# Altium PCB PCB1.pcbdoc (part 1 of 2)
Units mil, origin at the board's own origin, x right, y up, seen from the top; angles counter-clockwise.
Board outline 1855 x 1070 mil, 2 copper layers (Top Layer, Bottom Layer), stack 62.206 mil thick; 23 components, 23 nets, 105 pads, 33 vias.
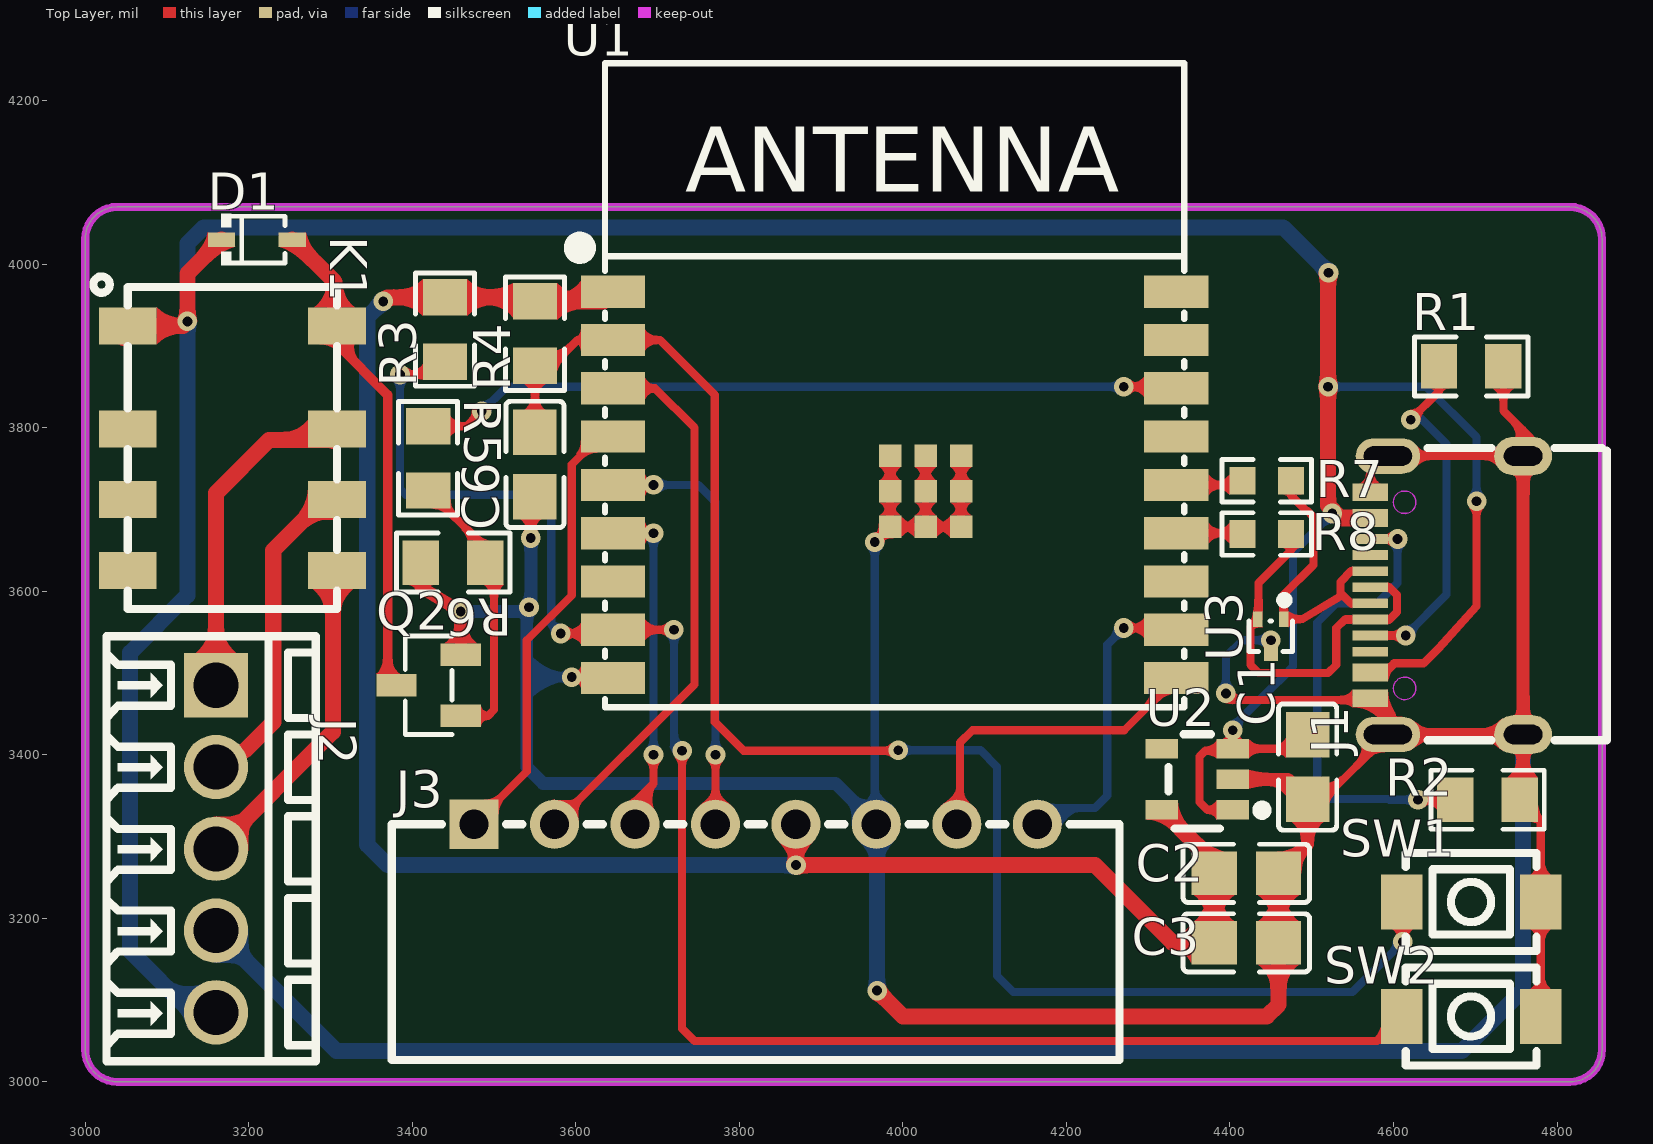
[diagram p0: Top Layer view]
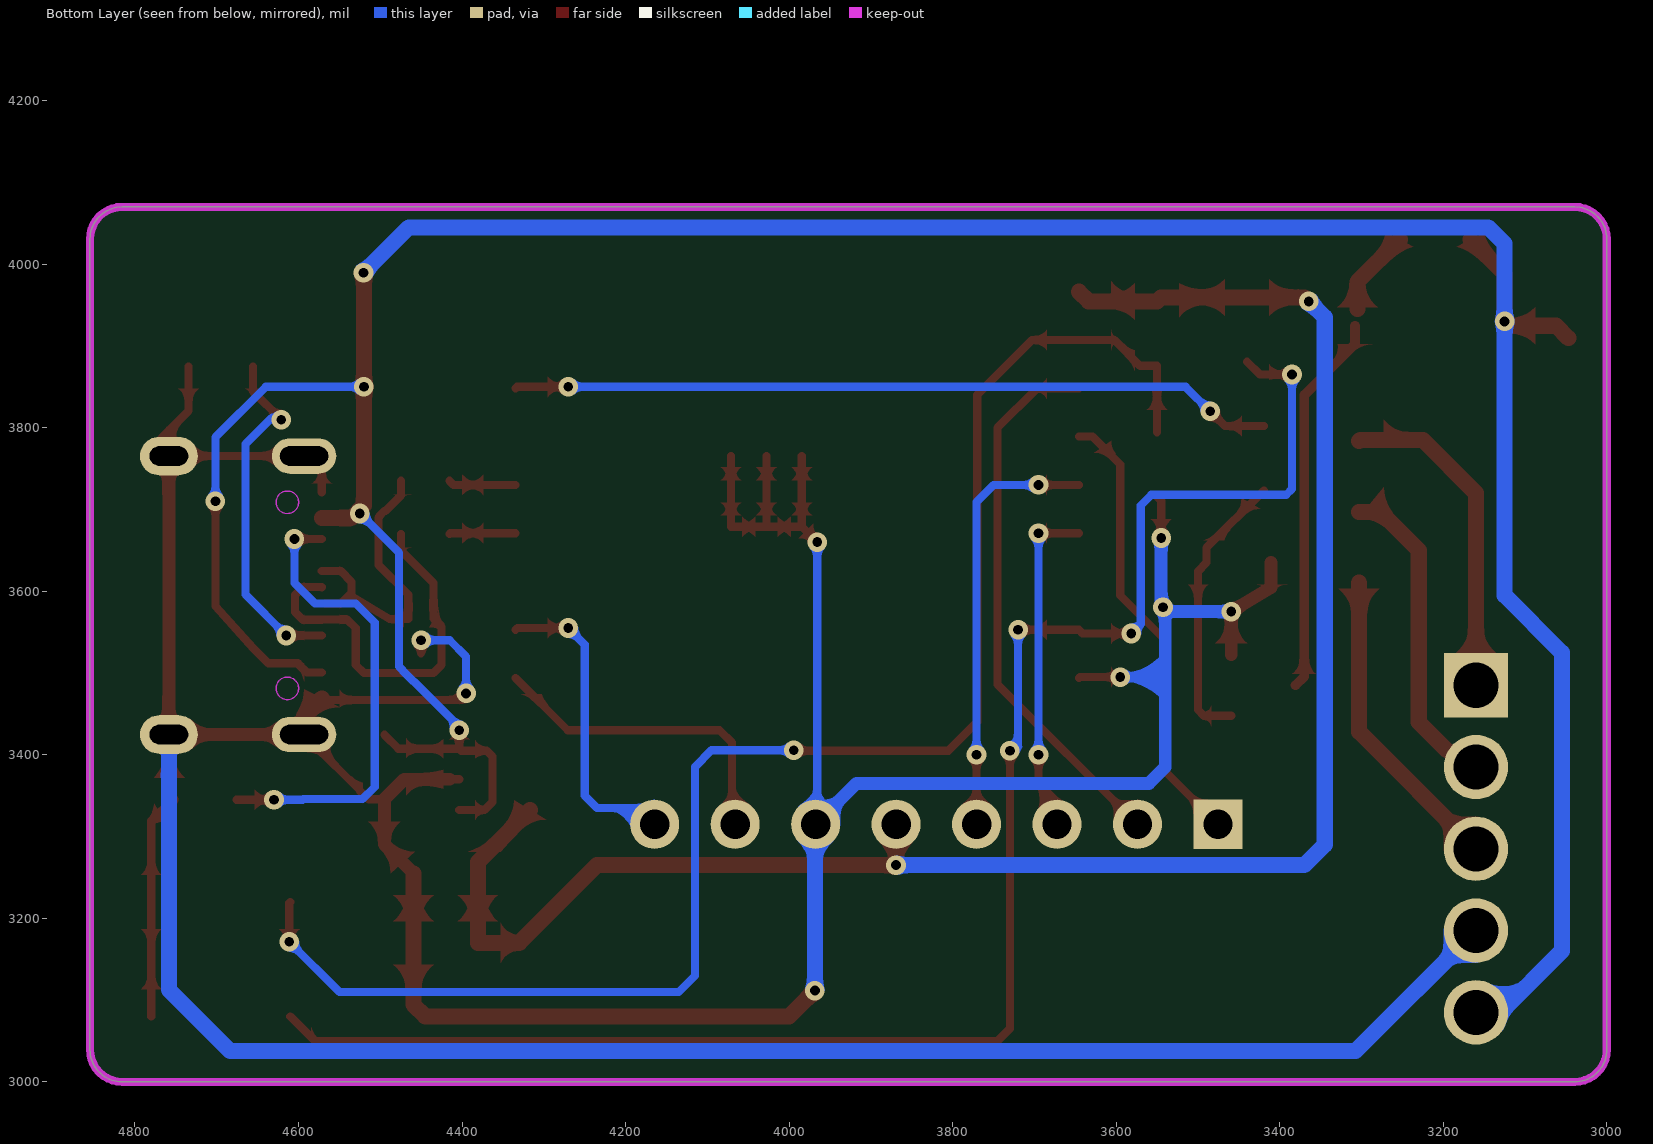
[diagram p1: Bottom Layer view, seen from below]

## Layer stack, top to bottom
Top Solder Mask Layer: solder mask 0.394, Dk 3.3
Top Layer: signal copper 1.379
Dielectric1: surface 59.449, FR4, Dk 4.5
Bottom Layer: signal copper 1.378
Bottom Solder Mask Layer: solder mask 0.394, Dk 3.3

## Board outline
3039.37,4070 4815.63,4070 cw(c4815.63,4030.63) 4855,4030.63 4855,3039.37 cw(c4815.63,3039.37) 4815.63,3000 3039.37,3000 cw(c3039.37,3039.37) 3000,3039.37 3000,4030.63 cw(c3039.37,4030.63)

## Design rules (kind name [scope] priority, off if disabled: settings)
BoardOutlineClearance copperThickness1oz [All] p0: genericclearance=10 ignorepadtopadclearanceinfootprint=FALSE except(0: Arc-SplitContinuation Track-SplitContinuation SMDPad-SplitContinuation THPad-SplitContinuation Via-SplitContinuation Fill-SplitContinuation Poly-SplitContinuation Region-SplitContinuation Text-SplitContinuation)
BoardOutlineClearance copperThickness2oz [All] p0: genericclearance=10 ignorepadtopadclearanceinfootprint=FALSE except(0: Arc-SplitContinuation Track-SplitContinuation SMDPad-SplitContinuation THPad-SplitContinuation Via-SplitContinuation Fill-SplitContinuation Poly-SplitContinuation Region-SplitContinuation Text-SplitContinuation)
BoardOutlineClearance otherClearance [All] p0: genericclearance=10 ignorepadtopadclearanceinfootprint=FALSE except(0: Arc-SplitContinuation Track-SplitContinuation SMDPad-SplitContinuation THPad-SplitContinuation Via-SplitContinuation Fill-SplitContinuation Poly-SplitContinuation Region-SplitContinuation Text-SplitContinuation)
Clearance copperThickness1oz [All] p1: gap=7 ignorepadtopadclearanceinfootprint=FALSE
Clearance copperThickness2oz [All] p1: gap=7 ignorepadtopadclearanceinfootprint=FALSE
Clearance otherClearance [All] p1: gap=7 ignorepadtopadclearanceinfootprint=FALSE
DiffPairsRouting differentialPair [All] p1: maxuncoupledlength=10 minlimit=6 maxlimit=Infinity mostfreqgap=6 toplayer_minwidth=5 toplayer_prefwidth=10 toplayer_maxwidth=100 bottomlayer_minwidth=5 bottomlayer_prefwidth=10 bottomlayer_maxwidth=100
PasteMaskExpansion pasteMaskExpansion [All] p1: expansion=0
PlaneConnect innerPlane [All] p1: planeconnectstyle=Relief reliefexpansion=20 reliefentries=4 reliefconductorwidth=10 reliefairgap=10
PolygonConnect copperRegion [All] p1: connectstyle=Relief reliefentries=4 reliefconductorwidth=10 polygonreliefangle="90 Angle" airgapwidth=10
RoutingVias viaSize [All] p1: viastyle="Through Hole" holewidth=12.0078 minholewidth=11.811 maxholewidth=248.0314 width=12.0078 minwidth=11.811 maxwidth=248.0314
SolderMaskExpansion solderMaskExpansion [All] p1: useseparateexpansions=TRUE expansion=2 expansionbottom=2
Width copperThickness1oz [All] p1: maxlimit=100 minlimit=5 preferedwidth=10
Width copperThickness2oz [All] p1: maxlimit=100 minlimit=8 preferedwidth=10

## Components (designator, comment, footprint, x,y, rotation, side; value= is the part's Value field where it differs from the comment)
C1 "" C0805 4495,3385 r90 top
C2 "" C0805 4420,3255 r0 top
C3 "" C0805 4420,3170 r180 top
C6 "" C0805 3550,3755 r90 top
D1 "" SOD-323_L1.7-W1.3-LS2.7-RD 3210,4030 r0 top
J1 "" USB-C-SMD_TYPE-C-6PIN-2MD-073 4665,3595 r90 top
J2 "" CONN-TH_XY308-2.54-5P 3160,3285 r270 top
J3 "" CONN-TH_8P-P2.50_ZX-XH2.54-8PWZ 3820,3315 r0 top
K1 "" RELAY-SMD_HFD4-5-S 3180,3775 r270 top
Q2 "" SOT-23-3_L2.9-W1.3-P1.90-LS2.4-BR 3420,3485 r0 top
R1 "" R0805 4695,3875 r0 top
R2 "" R0805 4715,3345 r0 top
R3 "" R0805 3440,3920 r90 top
R4 "" R0805 3550,3915 r90 top
R5 "" R0805 3419.42,3762.53 r270 top
R6 "" R0805 3450,3635 r180 top
R7 "" R0603 4445,3735 r0 top
R8 "" R0603 4445,3670 r0 top
SW1 "" KEY-SMD_L4.0-W3.0-LS4.9-1 4695,3220 r0 top
SW2 "" KEY-SMD_L4.0-W3.0-LS4.9-1 4695,3080 r0 top
U1 "" BULETM-SMD_ESPRESSIF_ESP32-C3-WROOM-02-N4-4MB 3990,3730 r0 top
U2 "" SOT-23-5_L2.9-W1.6-P0.95-LS2.8-BR 4360,3370 r0 top
U3 "" SOT-723_L1.2-W0.8-P0.80-LS1.2-BR 4450,3545 r90 top

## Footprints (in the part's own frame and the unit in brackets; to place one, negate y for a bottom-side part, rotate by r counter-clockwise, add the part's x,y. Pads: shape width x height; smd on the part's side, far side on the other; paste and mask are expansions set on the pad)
BULETM-SMD_ESPRESSIF_ESP32-C3-WROOM-02-N4-4MB [mm]
  rect 2x1 smd: 1(-8.75,6) 2(-8.75,4.5) 3(-8.75,3) 4(-8.75,1.5) 5(-8.75,0) 6(-8.75,-1.5) 7(-8.75,-3) 8(-8.75,-4.5) 9(-8.75,-6) 10(8.75,-6) 11(8.75,-4.5) 12(8.75,-3) 13(8.75,-1.5) 14(8.75,0) 15(8.75,1.5) 16(8.75,3) 17(8.75,4.5) 18(8.75,6)
  rect 0.7x0.7 smd: 19(-0.14,-1.3) 19(-0.14,-0.2) 19(-0.14,0.9) 19(0.96,-1.3) 19(0.96,-0.2) 19(0.96,0.9) 19(2.06,-1.3) 19(2.06,-0.2) 19(2.06,0.9)
  silkscreen extent -10.03,-6.9 9,13.1
C0805 [mm]
  rect 1.41x1.35 smd: 1(-1,0) 2(1,0)
  silkscreen extent -1.96,-0.9 1.96,0.9
CONN-TH_8P-P2.50_ZX-XH2.54-8PWZ [mil]
  rect 60x60 hole 36: 1(-344.49,0)
  round 60 hole 36: 2(-246.07,0) 3(-147.64,0) 4(-49.22,0) 5(49.21,0) 6(147.64,0) 7(246.06,0) 8(344.48,0)
  silkscreen extent -445,-288 445,0
CONN-TH_XY308-2.54-5P [mm]
  rect 2x2 hole 1.4: 1(-5.08,0)
  round 2 hole 1.4: 2(-2.54,0) 3(0,0) 4(2.54,0) 5(5.08,0)
  silkscreen extent -6.6,-3.4 6.6,3.1
KEY-SMD_L4.0-W3.0-LS4.9-1 [mm]
  rect 1.3x1.7 smd: 1(-2.159,0) 2(2.159,0)
  silkscreen extent -2.03,-1.52 2.03,1.52
R0603 [mil]
  rect 31.75x34.02 smd: 1(-29.66,0) 2(29.66,0)
  silkscreen extent -55,-26 55,26
R0805 [mm]
  rect 1.133x1.377 smd: 1(-1,0) 2(1,0)
  silkscreen extent -1.76,-0.92 1.76,0.92
RELAY-SMD_HFD4-5-S [mm]
  rect 1.15x1.8 smd: 1(-3.8,-3.25) 2(-0.6,-3.25) 3(1.6,-3.25) 4(3.8,-3.25) 5(3.8,3.25) 6(1.6,3.25) 7(-0.6,3.25) 8(-3.8,3.25)
  silkscreen extent -5.33,-4.32 5,3.25
SOD-323_L1.7-W1.3-LS2.7-RD [mm]
  rect 0.845x0.455 smd: 1(-1.098,0) 2(1.098,0)
  silkscreen extent -1.1,-0.8 0.88,0.8
SOT-23-3_L2.9-W1.3-P1.90-LS2.4-BR [mm]
  rect 1.25x0.7 smd: 1(1,-0.95) 2(1,0.95) 3(-1,0)
  silkscreen extent -0.73,-1.53 0.73,1.53
SOT-23-5_L2.9-W1.6-P0.95-LS2.8-BR [mm]
  rect 1x0.6 smd: 1(1.1,-0.95) 2(1.1,0) 3(1.1,0.95) 4(-1.1,0.95) 5(-1.1,-0.95)
  silkscreen extent -0.89,-1.52 2.16,1.4
SOT-723_L1.2-W0.8-P0.80-LS1.2-BR [mil]
  rect 19.25x11.57 smd: 1(20.85,-15.75) 2(20.85,15.75)
  rect 19.25x17.09 smd: 3(-20.85,0)
  silkscreen extent -19,-27 49,27
USB-C-SMD_TYPE-C-6PIN-2MD-073 [mm]
  rect 0.55x1.1 smd: 1(-3.2,2.375) 2(-2.4,2.375) 11(2.4,2.375) 12(3.2,2.375)
  rect 0.3x1.1 smd: 3(-1.75,2.375) 4(-1.25,2.375) 5(-0.75,2.375) 6(-0.25,2.375) 7(0.25,2.375) 8(0.75,2.375) 9(1.25,2.375) 10(1.75,2.375)
  oval 1.2x1.8 hole 0.6 slot 1.2 at 90 deg: 13(-4.325,-2.375) 14(4.325,-2.375)
  oval 1.1x2 hole 0.6 slot 1.5 at 90 deg: 13(-4.325,1.825) 14(4.325,1.825)
  Board Outline Layer circle w0.003: c-2.89,1.305 r0.35
  Board Outline Layer circle w0.003: c2.89,1.305 r0.35
  Board Outline Layer region: -2.89,0.955 -3.042,0.99 -3.164,1.087 -3.231,1.227 -3.231,1.383 -3.164,1.523 -3.042,1.62 -2.89,1.655 -2.89,1.655 -2.738,1.62 -2.616,1.523 -2.549,1.383 -2.549,1.227 -2.616,1.087 -2.738,0.99 -2.89,0.955
  Board Outline Layer region: -2.89,0.955 -3.042,0.99 -3.164,1.087 -3.231,1.227 -3.231,1.383 -3.164,1.523 -3.042,1.62 -2.89,1.655 -2.89,1.655 -2.738,1.62 -2.616,1.523 -2.549,1.383 -2.549,1.227 -2.616,1.087 -2.738,0.99 -2.89,0.955
  Board Outline Layer region: 2.89,0.955 2.738,0.99 2.616,1.087 2.549,1.227 2.549,1.383 2.616,1.523 2.738,1.62 2.89,1.655 2.89,1.655 3.042,1.62 3.164,1.523 3.231,1.383 3.231,1.227 3.164,1.087 3.042,0.99 2.89,0.955
  Board Outline Layer region: 2.89,0.955 2.738,0.99 2.616,1.087 2.549,1.227 2.549,1.383 2.616,1.523 2.738,1.62 2.89,1.655 2.89,1.655 3.042,1.62 3.164,1.523 3.231,1.383 3.231,1.227 3.164,1.087 3.042,0.99 2.89,0.955
  silkscreen extent -4.5,-4.97 4.57,0.6

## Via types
v1: diameter 24.02, hole 12.01, Top Layer to Bottom Layer, 33 vias

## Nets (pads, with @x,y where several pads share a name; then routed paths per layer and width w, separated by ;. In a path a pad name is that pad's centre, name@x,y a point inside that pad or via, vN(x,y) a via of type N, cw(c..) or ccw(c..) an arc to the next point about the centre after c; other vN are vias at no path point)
3V3: C2.1 C3.2 J3.5 R3.2 R4.2 U1.1 U2.5 | length 2287
  Top Layer w19.68: v1(3364.45,3954.45) 3369.37,3959.37 R3.2@3440,3959.37 3545,3959.37 R4.2@3550,3954.37 3633.66,3954.37 U1.1@3645.51,3966.22 ; J3.5@3869.21,3315 v1(3869.21,3265) 4235,3265 4330,3170 C3.2@4380.63,3170 C2.1@4380.63,3255 4380.63,3268.65 U2.5@4316.69,3332.59
  Bottom Layer w19.68: v1(3364.45,3954.45) 3345,3935 3345,3290 3370,3265 v1(3869.21,3265)
$1N8: R8.1 U1.13 | length 81.2
  Top Layer w10: U1.13@4334.49,3670.95 4414.39,3670.95 R8.1@4415.34,3670
$1N15: C6.2 R4.1 SW1.1 U1.2 | length 1944.9
  Top Layer w10: C6.2@3550,3794.37 R4.1@3550,3875.63 3570.63,3875.63 3602.17,3907.17 U1.2@3645.51,3907.17 3702.83,3907.17 3770,3840 3770,3440 3805,3405 3993.88,3405 v1(3994.44,3405.56) ; SW1.1@4610,3220 4611.26,3218.74 v1(4611.26,3171.26)
  Bottom Layer w10: v1(3994.44,3405.56) 4095,3405.56 4115.28,3385.28 4115.28,3129.72 4135,3110 4550,3110 v1(4611.26,3171.26)
$1N24: R3.1 SW2.1 U1.8 | length 2090.2
  Top Layer w10: v1(3385,3865) 3424.37,3865 R3.1@3440,3880.63 ; v1(3581.65,3548.35) 3641.02,3548.35 U1.8@3645.51,3552.84 v1(3720,3552.84) ; v1(3730,3405) 3730,3332.17 3729.81,3331.98 3729.81,3298.02 3730,3297.83 3730,3065 3745,3050 4580,3050 SW2.1@4610,3080
  Bottom Layer w10: v1(3385,3865) 3385,3725 3392.07,3717.93 3557.07,3717.93 3570,3705 3570,3560 v1(3581.65,3548.35) ; v1(3720,3552.84) 3720,3410 3725,3405 v1(3730,3405)
$1N26: J1.4 R1.1 | length 435.9
  Top Layer w10: J1.4@4571.49,3545.8 v1(4615,3545.8) ; v1(4621.12,3809.74) 4655.63,3844.25 R1.1@4655.63,3875
  Bottom Layer w10: v1(4615,3545.8) 4665,3595.8 4665,3780 4633.19,3811.81 4623.19,3811.81 v1(4621.12,3809.74)
$1N27: J1.10 R2.1 | length 582.1
  Top Layer w10: J1.10@4571.49,3663.91 v1(4605,3663.91) ; v1(4630,3345) R2.1@4675.63,3345
  Bottom Layer w10: v1(4605,3663.91) 4605,3610 4580,3585 4530,3585 4506.71,3561.71 4506.71,3360.72 4521.67,3345.76 4594.24,3345.76 4595,3345 v1(4630,3345)
$1N36: Q2.1 R5.2 R6.1 | length 345.2
  Top Layer w10: R5.2@3419.42,3723.16 3489.37,3653.22 R6.1@3489.37,3635 3500,3624.37 3500,3455 3492.6,3447.6 Q2.1@3459.37,3447.6
$1N58: D1.2 K1.8 Q2.3 | length 576.2
  Top Layer w11.81: K1.8@3307.95,3924.61 3307.95,3902.05 3370,3840 3370,3495.63 Q2.3@3380.63,3485
  Top Layer w19.68: D1.2@3253.21,4030 3305,3978.21 K1.8@3305,3945
$1N67: R7.1 U1.14 | length 82.9
  Top Layer w10: U1.14@4334.49,3730 4410.34,3730 R7.1@4415.34,3735
+5V: C1.2 D1.1 J1.2 J1.11 J2.5 K1.1 U2.1 U2.3 | length 4164.1
  Top Layer w10: U2.1@4403.31,3332.61 4372.4,3332.61 4362.93,3342.07 4362.93,3397.93 4370,3405 4400.91,3405 U2.3@4403.31,3407.39 ; v1(4403.31,3430) U2.3@4403.31,3407.39 ; C1.2@4495,3424.37 4478.02,3407.39 U2.3@4403.31,3407.39 ; J1.2@4571.49,3500.51 4589.65,3500.51 4600.95,3511.82 4636.82,3511.82 4655,3530 4701.63,3581.63 v1(4701.63,3710)
  Top Layer w19.68: K1.1@3047.05,3909.61 3062.05,3924.61 3119.61,3924.61 v1(3125,3930) 3125,3988.21 D1.1@3166.79,4030 ; v1(4520.57,3989.43) 4520,3988.85 v1(4520,3850) 4520,3705 4535.51,3689.49 J1.11@4571.49,3689.49
  Bottom Layer w10: v1(4403.31,3430) 4403.31,3434.16 4458.75,3489.61 4459.52,3489.61 4472.99,3503.08 4472.99,3503.85 4477.13,3507.99 4477.13,3647.13 v1(4525,3695) ; v1(4520,3850) 4640,3850 4701.63,3788.37 v1(4701.63,3710)
  Bottom Layer w19.68: J2.5@3160,3085 3130,3085 3055,3160 3055,3525 3125,3595 v1(3125,3930) 3125,4025 3145,4045 4465,4045 v1(4520.57,3989.43)
COM: J2.2 K1.6 | length 351.9
  Top Layer w19.68: 3195,3405 3230,3440 3230,3650 3277.01,3697.01 K1.6@3302.95,3697.01
GND: C1.1 C2.2 C3.1 C6.1 J1.1 J1.12 J1.13 J1.14 J2.4 J3.6 Q2.2 R1.2 R2.2 R6.2 SW1.2 SW2.2 U1.9 U1.19 U2.2 U3.3 | length 6590.5
  Top Layer w10: v1(3545,3665) 3545,3710.63 C6.1@3550,3715.63 ; v1(3595,3495) 3644.29,3495 U1.9@3645.51,3493.78 ; v1(3965.66,3659.99) U1.19@3984.49,3678.82 ; U1.19@3984.49,3765.44 U1.19@3984.49,3722.13 U1.19@3984.49,3678.82 ; U1.19@4027.79,3765.44 U1.19@4027.79,3722.13 U1.19@4027.79,3678.82 ; U1.19@4071.1,3765.44 U1.19@4071.1,3722.13 U1.19@4071.1,3678.82 U1.19@4027.79,3678.82 ; v1(4395,3475) 4402.99,3467.01 4569.49,3467.01 J1.1@4571.49,3469.01 ; U2.2@4403.31,3369.99 U2.2@4414.99,3369.99 ; U3.3@4450,3524.15 v1(4450,3540) ; C1.1@4495,3345.63 4514.05,3345.63 J1.13@4593.15,3424.73 ; J1.12@4571.49,3720.99 4571.49,3743.62 J1.14@4593.15,3765.28 J1.14@4758.51,3765.28 ; R1.2@4734.37,3875 4734.37,3820.63 J1.14@4767.5,3787.5 ; R2.2@4754.37,3345 4780,3319.37 SW1.2@4780,3220 SW2.2@4780,3080 ; U1.19@3984.49,3678.82 U1.19@4027.79,3678.82
  Top Layer w15.75: R6.2@3410.63,3635 3410.63,3604.37 v1(3459.37,3575) Q2.2@3459.37,3522.4 ; U2.2@4414.99,3369.99 4470.64,3369.99 C1.1@4495,3345.63 4495,3290.63 C2.2@4459.37,3255 ; J1.13@4593.15,3424.73 J1.13@4758.51,3424.72 ; R2.2@4754.37,3345 4758.51,3349.14 J1.13@4758.51,3424.72 ; J1.14@4758.51,3765.28 J1.13@4758.51,3424.72
  Top Layer w19.68: v1(3968.47,3111.53) 4000,3080 4445,3080 4459.37,3094.37 C3.1@4459.37,3170 C2.2@4459.37,3255 ; J1.1@4571.49,3469.01 4593.15,3447.36 J1.13@4593.15,3424.73
  Bottom Layer w10: 3540,3495.86 3540.86,3495 v1(3595,3495) ; J3.6@3965.66,3316.98 v1(3965.66,3659.99) ; v1(4395,3475) 4395,3520 4415,3540 v1(4450,3540)
  Bottom Layer w15.75: v1(3459.37,3575) 3537.42,3575 v1@3540,3577.58 ; v1(3545,3665) 3545,3582.58 v1(3542.73,3580.3) v1@3540,3577.58 ; J3.6@3967.64,3315 3965.66,3316.98 3917.64,3365 3560,3365 3540,3385 3540,3495.86 v1@3540,3577.58
  Bottom Layer w19.68: J2.4@3160,3185 3307.37,3037.63 4683.49,3037.63 4758.51,3112.65 J1.13@4758.51,3424.72 ; v1(3968.47,3111.53) J3.6@3968.47,3314.17
GPIO2: R5.1 U1.16 | length 935.8
  Top Layer w10: R5.1@3419.42,3801.9 3466.9,3801.9 v1(3485,3820) ; v1(4270,3850) 4332.6,3850 U1.16@4334.49,3848.11
  Bottom Layer w10: v1(3485,3820) 3515,3850 v1(4270,3850)
IRQ: J3.7 U1.10 | length 398.8
  Top Layer w10: J3.7@4066.06,3315 4070,3318.94 4070,3415 4085,3430 4270.71,3430 U1.10@4334.49,3493.78
MISO: J3.2 U1.3 | length 675.3
  Top Layer w10: J3.2@3573.93,3315 3745,3486.06 3745,3800 3696.89,3848.11 U1.3@3645.51,3848.11
MOSI: J3.3 U1.6 | length 414.8
  Top Layer w10: U1.6@3645.51,3670.95 v1(3695,3670.95) ; J3.3@3672.36,3315 3672.36,3342.36 3695,3365 v1(3695,3400)
  Bottom Layer w10: v1(3695,3400) v1(3695,3670.95)
NC: J2.1 K1.7 | length 405.4
  Top Layer w19.68: J2.1@3160,3485 3160,3720 3225,3785 3301.56,3785 K1.7@3302.95,3783.61
NO: J2.3 K1.5 | length 384.6
  Top Layer w19.68: J2.3@3160,3285 3302.95,3427.95 K1.5@3302.95,3610.39
RST: J3.8 U1.11 | length 378.7
  Top Layer w10: v1(4270,3555) 4332.33,3555 U1.11@4334.49,3552.84
  Bottom Layer w10: J3.8@4164.48,3315 4184.49,3335 4235,3335 4250,3350 4250,3535 v1(4270,3555)
SCK: J3.1 U1.4 | length 554.1
  Top Layer w10: J3.1@3475.51,3315 3540,3379.49 3540,3540 3595,3595 3595,3755 3629.06,3789.06 U1.4@3645.51,3789.06
SS: J3.4 U1.5 | length 528.1
  Top Layer w10: U1.5@3645.51,3730 v1(3695,3730) ; J3.4@3770.78,3315 v1(3770.79,3400)
  Bottom Layer w10: v1(3695,3730) 3750,3730 3770.79,3709.21 v1(3770.79,3400)
USB_D+: J1.6 J1.8 R7.2 U3.1 | length 368
  Top Layer w10: R7.2@4474.66,3735 4474.66,3716.86 4493.53,3697.99 4495.09,3697.99 4501.52,3691.56 4501.52,3690 4502.01,3689.51 4502.01,3632.01 4465.75,3595.75 U3.1@4465.75,3565.85 4488.69,3565.85 4536.63,3594.67 ; J1.6@4566.85,3585 4547.85,3585 4535,3597.85 4535,3611.44 4548.08,3624.53 J1.8@4571.49,3624.53
USB_D-: J1.5 J1.7 R8.2 U3.2 | length 479
  Top Layer w10: R8.2@4474.66,3670 4474.66,3649.66 4435,3610 4435,3566.6 U3.2@4434.25,3565.85 4425,3556.6 4425,3510 4435,3500 4520,3500 4530,3510 4530,3555 4540.48,3565.47 J1.5@4571.49,3565.47 4571.97,3565 4594.43,3565 4604.13,3574.7 4604.13,3595.61 4594.74,3605 4571.65,3605 J1.7@4571.49,3604.84
pads on no net: J1.3 J1.9 K1.2 K1.3 K1.4 U1.7 U1.12 U1.15 U1.17 U1.18 U2.4

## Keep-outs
Board Outline Layer:
  the board outline again, w10

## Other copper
Top Layer:
  region net GND: 4502.87,3294.25 4487.13,3294.25 ccw(c4457.6,3294.25) 4475.31,3317.87 4514.69,3317.87 ccw(c4532.4,3294.25)
  region net GND: 4483.16,3289.93 4495.48,3279.97 ccw(c4528.88,3254.92) 4487.13,3254.92 4458.11,3281.57 ccw(c4458.11,3323.33)
  region net GND: 4469.21,3198.9 4449.53,3198.9 ccw(c4412.62,3198.9) 4434.76,3228.43 4483.98,3228.43 ccw(c4506.12,3198.9)
  region net 3V3: 4390.47,3198.9 4370.79,3198.9 ccw(c4333.88,3198.9) 4356.02,3228.43 4405.24,3228.43 ccw(c4427.38,3198.9)
  region net 3V3: 4332.45,3302.91 4366.09,3297.11 ccw(c4409.55,3340.57) 4392.31,3281.57 4352.87,3281.57 ccw(c3855.06,2825.52)
  region net 3V3: 4330,3160.16 4330,3179.84 ccw(c4330,3204.94) 4352.87,3194.61 4352.87,3145.39 ccw(c4330,3135.06)
  region net 3V3: 4370.79,3226.1 4390.47,3226.1 ccw(c4427.38,3226.1) 4405.24,3196.57 4356.02,3196.57 ccw(c4333.88,3226.1)
  region net GND: 4469.21,3113.9 4449.53,3113.9 ccw(c4412.62,3113.9) 4434.76,3143.43 4483.98,3143.43 ccw(c4506.12,3113.9)
  region net GND: 4449.53,3226.1 4469.21,3226.1 ccw(c4506.12,3226.1) 4483.98,3196.57 4434.76,3196.57 ccw(c4412.62,3226.1)
  region net $1N15: 3545,3837.13 3555,3837.13 ccw(c3573.75,3837.13) 3562.5,3822.13 3537.5,3822.13 ccw(c3526.25,3837.13)
  region net GND: 3550,3672.87 3540,3672.87 ccw(c3521.25,3672.87) 3532.5,3687.87 3557.5,3687.87 ccw(c3568.75,3672.87)
  region net $1N26: 4608.15,3550.8 4608.15,3540.8 ccw(c4608.15,3416.1) 4593.15,3539.89 4593.15,3551.7 ccw(c4608.15,3675.49)
  region net USB_D-: 4594.43,3570 4594.43,3560 ccw(c4594.43,3557.87) 4593.15,3559.57 4593.15,3571.38 ccw(c4594.53,3571.38)
  region net $1N27: 4605,3668.91 4605,3658.91 ccw(c4605,3580.89) 4593.15,3658 4593.15,3669.81 ccw(c4605,3746.92)
  region net +5V: 4535.51,3679.65 4535.51,3699.34 ccw(c4535.51,3804.21) 4549.84,3700.32 4549.84,3678.67 ccw(c4535.51,3574.78)
  region net GND: 4566.49,3743.62 4576.49,3743.62 ccw(c4589.55,3743.62) 4583.99,3731.81 4558.99,3731.81 ccw(c4553.44,3743.62)
  region net GND: 4643.54,3770.28 4643.54,3760.28 4641.61,3760.11 4639.53,3759.63 4637.36,3758.89 4635.22,3757.93 4633.18,3756.8 4631.32,3755.53 4629.75,3754.17 4628.54,3752.78 4628.54,3777.78 4629.75,3776.38 4631.32,3775.02 4633.18,3773.75 4635.22,3772.62 4637.36,3771.66 4639.53,3770.92 4641.61,3770.44
  region net GND: 4711.65,3760.28 4711.65,3770.28 4713.94,3770.48 4716.28,3771.05 4718.57,3771.9 4720.73,3772.96 4722.71,3774.15 4724.4,3775.4 4725.74,3776.64 4726.65,3777.78 4726.65,3752.78 4725.74,3753.91 4724.4,3755.15 4722.71,3756.4 4720.73,3757.59 4718.57,3758.65 4716.28,3759.5 4713.94,3760.07
  region net $1N36: 3492.6,3452.6 3492.6,3442.6 ccw(c3492.6,3433.89) 3483.98,3435.1 3483.98,3460.1 ccw(c3492.6,3461.31)
  region net GND: 3451.5,3559.8 3467.24,3559.8 ccw(c3496.77,3559.8) 3479.05,3536.18 3439.68,3536.18 ccw(c3421.97,3559.8)
  region net $1N27: 4638.34,3340 4638.34,3350 ccw(c4638.34,3368.75) 4653.34,3357.5 4653.34,3332.5 ccw(c4638.34,3321.25)
  region net 3V3: 3383.37,3949.53 3383.37,3969.21 ccw(c3383.37,4010.45) 3412.89,3981.66 3412.89,3937.08 ccw(c3383.37,3908.29)
  region net 3V3: 3496.63,3969.21 3496.63,3949.53 ccw(c3496.63,3908.29) 3467.11,3937.08 3467.11,3981.66 ccw(c3496.63,4010.45)
  region net $1N24: 3397.89,3860 3397.89,3870 ccw(c3397.89,3888.75) 3412.89,3877.5 3412.89,3858.34 ccw(c3397.89,3791.56)
  region net 3V3: 3606.63,3964.21 3606.63,3944.53 ccw(c3606.63,3903.29) 3577.11,3932.08 3577.11,3976.66 ccw(c3606.63,4005.45)
  region net 3V3: 3493.37,3949.53 3493.37,3969.21 ccw(c3493.37,4031.44) 3522.89,3976.66 3522.89,3934.76 ccw(c3493.37,3912.62)
  region net $1N15: 3555,3838.34 3545,3838.34 ccw(c3526.25,3838.34) 3537.5,3853.34 3562.5,3853.34 ccw(c3573.75,3838.34)
  region net $1N15: 3590.43,3902.5 3585,3882.93 ccw(c3607.08,3860.85) 3577.11,3869.61 3577.11,3894.61 ccw(c3568.35,3924.58)
  region net $1N36: 3451.83,3697.82 3439.95,3695.56 ccw(c3424.04,3674.35) 3424.04,3700.87 3446.53,3713.73 ccw(c3473.05,3713.73)
  region net GPIO2: 3461.53,3806.9 3461.53,3796.9 ccw(c3461.53,3778.15) 3446.53,3789.4 3446.53,3814.4 ccw(c3461.53,3825.65)
  region net GND: 3418.5,3604.37 3402.76,3604.37 ccw(c3390.95,3586.34) 3390.95,3607.89 3430.32,3607.89 ccw(c3430.32,3586.34)
  region net $1N36: 3505,3592.89 3495,3592.89 ccw(c3476.25,3592.89) 3487.5,3607.89 3511.66,3607.89 ccw(c3525.21,3592.89)
  region net $1N36: 3460.09,3675.43 3479.66,3670 ccw(c3501.74,3692.08) 3492.98,3662.11 3467.98,3662.11 ccw(c3438.01,3653.35)
  region net $1N15: 4616.26,3171.54 4606.26,3171.54 ccw(c4587.51,3171.54) 4598.76,3186.54 4623.76,3186.54 ccw(c4635.01,3171.54)
  region net $1N24: 4583.54,3046.46 4576.52,3053.59 ccw(c4554.44,3075.67) 4584.41,3066.91 4584.41,3046.54 ccw(c4584.01,3045.99)
  region net 3V3: 3576.61,3944.53 3576.61,3964.21 ccw(c3576.61,4001.12) 3606.14,3978.98 3606.14,3946.53 ccw(c3606.14,3728.38)
  region net $1N15: 3602.17,3902.17 3602.17,3912.17 ccw(c3597.07,3919.67) 3606.14,3919.67 3606.14,3894.67 ccw(c3597.07,3894.67)
  region net $1N15: 3699.88,3912.17 3699.88,3902.17 ccw(c3699.88,3883.42) 3684.88,3894.67 3684.88,3919.67 ccw(c3699.88,3930.92)
  region net MISO: 3696.89,3853.11 3696.89,3843.11 ccw(c3696.89,3829.74) 3684.88,3835.61 3684.88,3860.61 ccw(c3696.89,3866.48)
  region net SCK: 3611.14,3764.07 3600.84,3767.91 ccw(c3579.62,3783.82) 3606.14,3783.82 3627.05,3769.38 ccw(c3627.05,3742.86)
  region net SS: 3695,3735 3695,3725 ccw(c3695,3714.42) 3684.88,3717.5 3684.88,3742.5 ccw(c3695,3745.58)
  region net MOSI: 3695,3675.95 3695,3665.95 ccw(c3695,3655.37) 3684.88,3658.45 3684.88,3683.45 ccw(c3695,3686.53)
  region net $1N24: 3591.14,3543.35 3591.14,3553.35 ccw(c3591.14,3572.1) 3606.14,3560.85 3606.14,3535.85 ccw(c3591.14,3524.6)
  region net $1N24: 3699.88,3557.84 3699.88,3547.84 ccw(c3699.88,3529.09) 3684.88,3540.34 3684.88,3565.34 ccw(c3699.88,3576.59)
  region net GND: 3595,3490 3595,3500 ccw(c3595,3512.02) 3606.14,3507.5 3606.14,3482.5 ccw(c3595,3477.98)
  region net IRQ: 4313.98,3466.2 4294.41,3460.77 ccw(c4272.33,3482.85) 4302.31,3474.09 4327.31,3474.09 ccw(c4336.06,3444.12)
  region net RST: 4280.12,3550 4280.12,3560 ccw(c4280.12,3578.75) 4295.12,3567.5 4295.12,3542.5 ccw(c4280.12,3531.25)
  region net GPIO2: 4280.12,3845 4280.12,3855 ccw(c4280.12,3873.75) 4295.12,3862.5 4295.12,3837.5 ccw(c4280.12,3826.25)
  region net GND: 3989.49,3736.66 3979.49,3736.66 ccw(c3960.74,3736.66) 3971.99,3751.66 3996.99,3751.66 ccw(c4008.24,3736.66)
  region net GND: 3989.49,3693.35 3979.49,3693.35 ccw(c3960.74,3693.35) 3971.99,3708.35 3996.99,3708.35 ccw(c4008.24,3693.35)
  region net GND: 3979.49,3750.91 3989.49,3750.91 ccw(c4008.24,3750.91) 3996.99,3735.91 3971.99,3735.91 ccw(c3960.74,3750.91)
  region net GND: 3979.49,3707.6 3989.49,3707.6 ccw(c4008.24,3707.6) 3996.99,3692.6 3971.99,3692.6 ccw(c3960.74,3707.6)
  region net GND: 3972.48,3659.74 3965.41,3666.81 ccw(c3944.19,3682.72) 3970.71,3682.72 3988.39,3665.04 ccw(c3988.39,3638.52)
  region net GND: 4013.27,3683.82 4013.27,3673.82 ccw(c4013.27,3655.07) 3998.27,3666.32 3998.27,3691.32 ccw(c4013.27,3702.57)
  region net GND: 4032.79,3736.66 4022.79,3736.66 ccw(c4004.04,3736.66) 4015.29,3751.66 4040.29,3751.66 ccw(c4051.54,3736.66)
  region net GND: 4032.79,3693.35 4022.79,3693.35 ccw(c4004.04,3693.35) 4015.29,3708.35 4040.29,3708.35 ccw(c4051.54,3693.35)
  region net GND: 4022.79,3750.91 4032.79,3750.91 ccw(c4051.54,3750.91) 4040.29,3735.91 4015.29,3735.91 ccw(c4004.04,3750.91)
  region net GND: 4022.79,3707.6 4032.79,3707.6 ccw(c4051.54,3707.6) 4040.29,3692.6 4015.29,3692.6 ccw(c4004.04,3707.6)
  region net GND: 3999.01,3673.82 3999.01,3683.82 ccw(c3999.01,3702.57) 4014.01,3691.32 4014.01,3666.32 ccw(c3999.01,3655.07)
  region net GND: 4056.57,3683.82 4056.57,3673.82 ccw(c4056.57,3655.07) 4041.57,3666.32 4041.57,3691.32 ccw(c4056.57,3702.57)
  region net GND: 4066.1,3707.6 4076.1,3707.6 ccw(c4094.85,3707.6) 4083.6,3692.6 4058.6,3692.6 ccw(c4047.35,3707.6)
  region net GND: 4042.32,3673.82 4042.32,3683.82 ccw(c4042.32,3702.57) 4057.32,3691.32 4057.32,3666.32 ccw(c4042.32,3655.07)
  region net GND: 4076.1,3693.35 4066.1,3693.35 ccw(c4047.35,3693.35) 4058.6,3708.35 4083.6,3708.35 ccw(c4094.85,3693.35)
  region net GND: 4066.1,3750.91 4076.1,3750.91 ccw(c4094.85,3750.91) 4083.6,3735.91 4058.6,3735.91 ccw(c4047.35,3750.91)
  region net GND: 4076.1,3736.66 4066.1,3736.66 ccw(c4047.35,3736.66) 4058.6,3751.66 4083.6,3751.66 ccw(c4094.85,3736.66)
  region net +5V: 4370,3400 4370,3410 ccw(c4370,3426.12) 4383.62,3417.5 4383.62,3395.58 ccw(c4370,3376.78)
  region net +5V: 4398.31,3430 4408.31,3430 ccw(c4419.82,3430) 4415.81,3419.21 4390.81,3419.21 ccw(c4386.79,3430)
  region net +5V: 4372.4,3327.61 4372.4,3337.61 ccw(c4372.4,3350.26) 4383.62,3344.42 4383.62,3320.79 ccw(c4372.4,3314.95)
  region net 3V3: 4348.46,3314.74 4326.67,3308.69 ccw(c4297,3278.34) 4297,3320.78 4336.37,3344.41 ccw(c4378.82,3344.41)
  region net SCK: 3503.74,3350.3 3510.81,3343.23 ccw(c3532.03,3327.32) 3505.51,3327.32 3487.83,3345 ccw(c3487.83,3371.52)
  region net MISO: 3599.28,3347.42 3606.36,3340.34 3605.35,3339.12 3604.56,3337.69 3603.95,3336.09 3603.51,3334.35 3603.05,3330.56 3603.02,3326.55 3603.25,3322.57 3603.58,3318.84 3603.84,3315.61 3603.88,3313.12 3572.06,3344.94 3574.55,3344.9 3577.78,3344.64 3581.51,3344.31 3585.49,3344.08 3589.5,3344.11 3593.29,3344.57 3595.03,3345.01 3596.63,3345.62 3598.06,3346.41
  region net MOSI: 3670.46,3347.53 3698.11,3361.04 3697.07,3359.8 3696.18,3358.33 3695.43,3356.66 3694.81,3354.84 3693.95,3350.85 3693.57,3346.64 3693.63,3342.52 3694.09,3338.75 3694.91,3335.62 3695.44,3334.39 3696.04,3333.42 3651.62,3336.67 3653.08,3337.76 3655.05,3338.8 3659.99,3341 3662.71,3342.28 3665.45,3343.75 3668.07,3345.48
  region net SS: 3765.79,3355.84 3775.79,3355.84 3775.95,3354.27 3776.39,3352.7 3777.1,3351.14 3778.02,3349.59 3780.37,3346.59 3783.18,3343.73 3786.16,3341.07 3789.03,3338.67 3791.5,3336.58 3793.29,3334.84 3748.29,3334.84 3750.08,3336.58 3752.55,3338.67 3755.42,3341.07 3758.4,3343.73 3761.21,3346.59 3763.56,3349.59 3764.48,3351.14 3765.19,3352.7 3765.63,3354.27
  region net 3V3: 3879.05,3274.16 3859.37,3274.16 3859.26,3275.74 3858.96,3277.32 3858.48,3278.9 3857.85,3280.46 3856.22,3283.52 3854.26,3286.43 3852.14,3289.11 3850.06,3291.51 3846.71,3295.16 3891.71,3295.16 3888.36,3291.51 3886.28,3289.11 3884.16,3286.43 3882.2,3283.52 3880.57,3280.46 3879.94,3278.9 3879.46,3277.32 3879.16,3275.74
  region net IRQ: 4065,3358.63 4075,3352.72 4075.15,3351.14 4075.57,3349.58 4076.22,3348.03 4077.08,3346.51 4079.28,3343.54 4081.88,3340.71 4087.24,3335.66 4089.44,3333.53 4090.97,3331.72 4046.36,3337.63 4051.06,3341.28 4054.12,3343.68 4057.27,3346.36 4060.22,3349.26 4062.68,3352.32 4063.64,3353.89 4064.37,3355.46 4064.84,3357.05
  region net GPIO2: 4286.35,3855 4286.35,3845 4284.54,3844.66 4282.27,3843.75 4279.94,3842.47 4277.94,3840.99 4277.94,3859.01 4279.94,3857.53 4282.27,3856.25 4284.54,3855.34
  region net GPIO2: 3476.98,3804.9 3469.9,3811.98 3470.94,3813.5 3471.9,3815.74 3472.64,3818.3 3473.02,3820.75 3485.75,3808.02 3483.3,3807.64 3480.74,3806.9 3478.5,3805.94
  region net RST: 4286.35,3560 4286.35,3550 4284.54,3549.66 4282.27,3548.75 4279.94,3547.47 4277.94,3545.99 4277.94,3564.01 4279.94,3562.53 4282.27,3561.25 4284.54,3560.34
  region net $1N26: 4598.65,3540.8 4598.65,3550.8 4600.46,3551.14 4602.73,3552.05 4605.06,3553.33 4607.06,3554.8 4607.06,3536.79 4605.06,3538.26 4602.73,3539.54 4600.46,3540.45
  region net $1N27: 4588.65,3658.91 4588.65,3668.91 4590.46,3669.25 4592.73,3670.16 4595.06,3671.44 4597.06,3672.91 4597.06,3654.9 4595.06,3656.37 4592.73,3657.65 4590.46,3658.56
  region net $1N27: 4646.35,3350 4646.35,3340 4644.54,3339.66 4642.27,3338.75 4639.94,3337.47 4637.94,3335.99 4637.94,3354.01 4639.94,3352.53 4642.27,3351.25 4644.54,3350.34
  region net GND: 3540,3681.35 3550,3681.35 3550.34,3679.54 3551.25,3677.27 3552.53,3674.94 3554.01,3672.94 3535.99,3672.94 3537.47,3674.94 3538.75,3677.27 3539.66,3679.54
  region net 3V3: 3883.62,3274.84 3883.62,3255.16 3881.47,3255.06 3879.35,3254.82 3875.35,3254.07 3871.88,3253.33 3869.21,3252.99 3869.21,3277.01 3871.88,3276.67 3875.35,3275.93 3879.35,3275.18 3881.47,3274.94
  region net 3V3: 3859.37,3279.41 3879.05,3279.41 3879.15,3277.26 3879.39,3275.14 3880.14,3271.14 3880.88,3267.67 3881.22,3265 3857.2,3265 3857.54,3267.67 3858.28,3271.14 3859.03,3275.14 3859.27,3277.26
  region net 3V3: 3377.77,3969.21 3383.44,3949.53 3377.88,3949.43 3375.95,3949.21 3375.34,3949.02 3375.03,3948.78 3369.36,3965.4 3370.07,3965.35 3370.91,3965.68 3372.94,3967.02 3375.27,3968.51 3376.51,3969.02
  region net GND: 3441.3,3576.69 3449.43,3590.18 3451.82,3588.86 3454.15,3587.75 3456.07,3587.02 3457.22,3586.81 3447.92,3571.39 3447.21,3572.3 3445.66,3573.66 3443.59,3575.2
  region net GND: 3467.24,3558.65 3451.5,3558.65 3451.4,3561.38 3451.14,3563.95 3450.78,3565.97 3450.36,3567.06 3468.38,3567.06 3467.96,3565.97 3467.6,3563.95 3467.34,3561.38
  region net GND: 3985.62,3108.3 3971.7,3094.38 3970.11,3095.84 3968.44,3097.17 3965.08,3099.47 3962.1,3101.39 3959.98,3103.04 3976.96,3120.02 3978.61,3117.9 3980.53,3114.92 3982.83,3111.56 3984.16,3109.89
  region net MOSI: 3678.65,3665.95 3678.65,3675.95 3680.46,3676.29 3682.73,3677.2 3685.06,3678.49 3687.06,3679.96 3687.06,3661.94 3685.06,3663.41 3682.73,3664.7 3680.46,3665.61
  region net SS: 3678.65,3725 3678.65,3735 3680.46,3735.34 3682.73,3736.25 3685.06,3737.53 3687.06,3739.01 3687.06,3720.99 3685.06,3722.47 3682.73,3723.75 3680.46,3724.66
  region net MOSI: 3700,3383.65 3690,3383.65 3689.66,3385.46 3688.75,3387.73 3687.47,3390.06 3685.99,3392.06 3704.01,3392.06 3702.53,3390.06 3701.25,3387.73 3700.34,3385.46
  region net SS: 3775.79,3383.65 3765.79,3383.65 3765.45,3385.46 3764.54,3387.73 3763.26,3390.06 3761.78,3392.06 3779.8,3392.06 3778.32,3390.06 3777.04,3387.73 3776.13,3385.46
  region net $1N24: 3703.65,3547.84 3703.65,3557.84 3705.46,3558.18 3707.73,3559.09 3710.06,3560.38 3712.06,3561.85 3712.06,3543.83 3710.06,3545.3 3707.73,3546.59 3705.46,3547.5
  region net $1N24: 3735,3388.65 3725,3388.65 3724.66,3390.46 3723.75,3392.73 3722.47,3395.06 3720.99,3397.06 3739.01,3397.06 3737.53,3395.06 3736.25,3392.73 3735.34,3390.46
  region net $1N24: 3401.35,3870 3401.35,3860 3399.54,3859.66 3397.27,3858.75 3394.94,3857.47 3392.94,3855.99 3392.94,3874.01 3394.94,3872.53 3397.27,3871.25 3399.54,3870.34
  region net $1N24: 3598,3553.35 3598,3543.35 3596.19,3543.01 3593.92,3542.1 3591.59,3540.81 3589.59,3539.34 3589.59,3557.36 3591.59,3555.88 3593.92,3554.6 3596.19,3553.69
  region net $1N15: 3978.52,3400 3977.68,3410 3979.55,3410.36 3981.84,3411.31 3984.15,3412.65 3986.08,3414.19 3986.93,3396.19 3984.87,3397.59 3982.52,3398.81 3980.27,3399.67
  region net $1N15: 4606.26,3187.61 4616.26,3187.61 4616.6,3185.8 4617.51,3183.53 4618.79,3181.2 4620.26,3179.2 4602.25,3179.2 4603.72,3181.2 4605.01,3183.53 4605.91,3185.8
  region net GND: 3611.35,3500 3611.35,3490 3609.54,3489.66 3607.27,3488.75 3604.94,3487.47 3602.94,3485.99 3602.94,3504.01 3604.94,3502.53 3607.27,3501.25 3609.54,3500.34
  region net GND: 3973.69,3675.09 3980.76,3668.02 3979.72,3666.5 3978.76,3664.25 3978.02,3661.7 3977.65,3659.24 3964.91,3671.98 3967.37,3672.35 3969.92,3673.09 3972.17,3674.05
  region net +5V: 4408.31,3413.65 4398.31,3413.65 4397.96,3415.46 4397.06,3417.73 4395.77,3420.06 4394.3,3422.06 4412.31,3422.06 4410.84,3420.06 4409.56,3417.73 4408.65,3415.46
  region net +5V: 4544.27,3699.34 4537.74,3679.65 4536.49,3679.86 4535.26,3680.4 4532.94,3681.98 4530.92,3683.44 4530.06,3683.82 4529.34,3683.8 4535.87,3700.11 4536.17,3699.85 4536.77,3699.66 4538.7,3699.44
  region net +5V: 4529.84,3835.59 4510.16,3835.59 4510.06,3837.74 4509.82,3839.86 4509.07,3843.86 4508.33,3847.33 4507.99,3850 4532.01,3850 4531.67,3847.33 4530.93,3843.86 4530.18,3839.86 4529.94,3837.74
  region net +5V: 4510.16,3708.25 4529.84,3714.03 4529.94,3708.47 4530.16,3706.54 4530.35,3705.93 4530.6,3705.62 4514.01,3699.84 4514.06,3700.55 4513.72,3701.4 4512.36,3703.42 4510.86,3705.75 4510.35,3706.99
  region net GND: 4446.61,3377.87 4446.61,3362.12 ccw(c4446.61,3289.29) 4422.99,3358.18 4422.99,3381.81 ccw(c4446.61,3450.7)
  region net GND: 4444.8,3362.12 4444.8,3377.87 ccw(c4468.43,3437.86) 4468.43,3373.39 4468.43,3350.31 ccw(c4444.8,3332.59)
  region net +5V: 4437.99,3412.39 4437.99,3402.39 ccw(c4437.99,3382.47) 4422.99,3395.58 4422.99,3419.21 ccw(c4437.99,3432.32)
  region net +5V: 4453.43,3402.39 4453.43,3412.39 ccw(c4453.43,3431.14) 4468.43,3419.89 4468.43,3396.61 ccw(c4453.43,3380.04)
  region net GND: 4415.37,3472.01 4403.34,3462.01 4400.85,3462.16 4398.51,3462.5 4396.49,3462.83 4394.93,3462.99 4406.96,3476.06 4407.21,3475.3 4407.78,3474.57 4408.64,3473.89 4409.72,3473.27 4410.99,3472.76 4412.38,3472.36 4413.86,3472.1
  region net GND: 4534.84,3462.01 4534.84,3472.01 ccw(c4534.84,3490.76) 4549.84,3479.51 4549.84,3458.19 ccw(c4534.84,3430.65)
  region net USB_D+: 4486.54,3570.85 4486.54,3560.85 ccw(c4486.54,3534.22) 4471.54,3556.22 4471.54,3575.48 ccw(c4486.54,3597.48)
  region net USB_D+: 4460.75,3590.48 4470.75,3590.48 ccw(c4614,3590.48) 4471.54,3575.48 4459.96,3575.48 ccw(c4317.5,3590.48)
  region net USB_D+: 4479.66,3716.86 4469.66,3716.86 ccw(c4462.16,3692.58) 4462.16,3717.99 4487.16,3717.99 ccw(c4487.16,3692.58)
  region net USB_D-: 4428.54,3553.06 4422.03,3560.7 ccw(c4406.46,3576.27) 4428.46,3575.48 4440.04,3556.22 ccw(c4440.04,3533.71)
  region net USB_D-: 4430,3590.48 4440,3590.48 ccw(c7439.79,3590.48) 4440.04,3575.48 4428.46,3575.48 ccw(c4356.06,3590.48)
  region net USB_D-: 4479.66,3649.66 4469.66,3649.66 ccw(c4462.16,3642.89) 4462.16,3652.99 4487.16,3652.99 ccw(c4487.16,3642.89)
  region net GND: 4775,3128.46 4785,3128.46 ccw(c4803.75,3128.46) 4792.5,3113.46 4767.5,3113.46 ccw(c4756.25,3128.46)
  region net GND: 4785,3171.54 4775,3171.54 ccw(c4756.25,3171.54) 4767.5,3186.54 4792.5,3186.54 ccw(c4803.75,3171.54)
  region net GND: 4781.97,3324.47 4776.46,3315.83 ccw(c4763.8,3277.91) 4763.8,3317.89 4776.66,3340.38 ccw(c4803.18,3340.38)
  region net GND: 4775,3268.46 4785,3268.46 ccw(c4803.75,3268.46) 4792.5,3253.46 4767.5,3253.46 ccw(c4756.25,3268.46)
  region net GND: 4445,3540 4455,3540 ccw(c4462.24,3540) 4458.54,3533.78 4441.46,3533.78 ccw(c4437.76,3540)
  region net GND: 4455,3524.15 4445,3524.15 4444.66,3525.78 4443.75,3527.88 4442.47,3530.1 4440.99,3532.06 4459.01,3532.06 4457.53,3530.1 4456.25,3527.88 4455.34,3525.78
  region net USB_D-: 4540.48,3560.47 4540.48,3570.47 ccw(c4540.48,3619.37) 4549.84,3571.38 4549.84,3559.57 ccw(c4540.48,3511.58)
  region net $1N67: 4384.46,3725 4384.46,3735 ccw(c4384.46,3753.75) 4399.46,3742.5 4399.46,3717.99 ccw(c4384.46,3705.44)
  region net $1N67: 4388.86,3735 4388.86,3725 ccw(c4388.86,3706.25) 4373.86,3717.5 4373.86,3742.5 ccw(c4388.86,3753.75)
  region net $1N8: 4388.86,3675.95 4388.86,3665.95 ccw(c4388.86,3647.2) 4373.86,3658.45 4373.86,3683.45 ccw(c4388.86,3694.7)
  region net $1N8: 4384.46,3665.95 4384.46,3675.95 ccw(c4384.46,3694.7) 4399.46,3683.45 4399.46,3658.45 ccw(c4384.46,3647.2)
  region net GND: 4739.37,3832.89 4729.37,3832.89 ccw(c4710.62,3832.89) 4721.87,3847.89 4746.87,3847.89 ccw(c4758.12,3832.89)
  region net GND: 4743.12,3804.81 4761.14,3800.93 4762.63,3799.2 4763.94,3797.26 4766.18,3793.32 4767.2,3791.59 4768.2,3790.18 4769.23,3789.24 4769.76,3788.99 4770.32,3788.9 4748.43,3788.9 4748.97,3789.03 4749.33,3789.41 4749.55,3790 4749.61,3790.79 4749.34,3792.81 4748.62,3795.26 4747.55,3797.91 4746.21,3800.53 4744.71,3802.91
  region net $1N26: 4660.63,3844.25 4650.63,3844.25 ccw(c4643.13,3838.35) 4643.13,3847.89 4668.13,3847.89 ccw(c4668.13,3838.35)
  region net $1N26: 4629.14,3824.84 4636.21,3817.76 4635.18,3816.24 4634.22,3814 4633.48,3811.44 4633.1,3808.99 4620.37,3821.72 4622.82,3822.1 4625.37,3822.84 4627.62,3823.8
  region net +5V: 4510.16,3864.41 4529.84,3864.41 4529.94,3862.26 4530.18,3860.14 4530.93,3856.14 4531.67,3852.67 4532.01,3850 4507.99,3850 4508.33,3852.67 4509.07,3856.14 4509.82,3860.14 4510.06,3862.26
  region net +5V: 4529.84,3974.45 4510.16,3975.59 4509.89,3979.87 4509.32,3983.87 4508.77,3987.34 4508.58,3990 4532.57,3988.85 4532.08,3986.18 4531.15,3982.71 4530.25,3978.72 4529.95,3976.6
  region net NO: 3312.79,3573.23 3293.1,3573.23 ccw(c3256.19,3573.23) 3278.34,3602.76 3327.55,3602.76 ccw(c3349.7,3573.23)
  region net NO: 3190.94,3329.86 3204.86,3315.94 3203.52,3314.36 3202.4,3312.54 3201.49,3310.54 3200.76,3308.38 3200.2,3306.1 3199.79,3303.73 3199.31,3298.85 3199.19,3294.02 3199.25,3289.51 3199.33,3285.59 3199.29,3282.53 3157.53,3324.29 3160.59,3324.33 3164.51,3324.25 3169.02,3324.19 3173.85,3324.31 3178.73,3324.79 3181.1,3325.2 3183.38,3325.76 3185.54,3326.49 3187.54,3327.4 3189.36,3328.52
  region net NC: 3150.16,3553.9 3169.84,3553.9 ccw(c3206.75,3553.9) 3184.61,3524.37 3135.39,3524.37 ccw(c3113.25,3553.9)
  region net NC: 3242.98,3775.16 3242.98,3794.84 ccw(c3242.98,3831.75) 3272.51,3809.61 3272.51,3775.98 ccw(c3272.51,3243.61)
  region net +5V: 3117.02,3934.45 3117.02,3914.76 ccw(c3117.02,3874.3) 3087.49,3901.97 3087.49,3947.24 ccw(c3117.02,3974.91)
  region net +5V: 3112.15,3914.76 3105.78,3934.45 3111.35,3934.55 3113.28,3934.77 3113.88,3934.96 3114.18,3935.21 3120.55,3918.85 3119.83,3918.87 3118.98,3918.5 3116.96,3917.06 3114.63,3915.5 3113.4,3914.97
  region net +5V: 3156.71,4006 3135.11,4012.24 ccw(c3094.84,4052.51) 3150.16,4038.96 3183.42,4021.04 ccw(c3196.98,3965.73)
  region net +5V: 3115.16,3944.41 3134.84,3944.41 3134.94,3942.26 3135.18,3940.14 3135.93,3936.14 3136.67,3932.67 3137.01,3930 3112.99,3930 3113.33,3932.67 3114.07,3936.14 3114.82,3940.14 3115.06,3942.26
  region net COM: 3272.85,3678.93 3262.07,3695.99 ccw(c3220.31,3727.31) 3272.51,3727.31 3304.17,3689.37 ccw(c3304.17,3637.17)
  region net $1N58: 3284.89,4012.24 3263.29,4006 ccw(c3223.02,3965.73) 3236.58,4021.04 3269.84,4038.96 ccw(c3325.16,4052.51)
  region net $1N58: 3295.16,3976.77 3314.84,3976.77 ccw(c3351.75,3976.77) 3329.61,3947.24 3280.39,3947.24 ccw(c3258.25,3976.77)
  region net $1N58: 3364.09,3516.5 3375.91,3516.5 ccw(c3398.05,3516.5) 3384.76,3498.78 3356.02,3498.78 ccw(c3340.61,3516.5)
  region net $1N58: 3335.18,3883.18 3305.95,3895.7 ccw(c3287.15,3870.65) 3287.15,3901.97 3328.91,3901.97 ccw(c3350.84,3898.84)
  region net GND: 4643.5,3432.6 4643.5,3416.85 4641.73,3416.74 4639.97,3416.43 4638.23,3415.95 4636.5,3415.32 4633.14,3413.69 4629.95,3411.77 4624.27,3407.81 4621.89,3406.18 4619.88,3405.04 4619.88,3444.41 4621.89,3443.27 4624.27,3441.64 4629.95,3437.68 4633.14,3435.76 4636.5,3434.14 4638.23,3433.5 4639.97,3433.02 4641.73,3432.71
  region net GND: 4710.01,3416.85 4710.01,3432.6 4711.79,3432.7 4713.56,3432.99 4717.07,3434.03 4720.48,3435.57 4723.72,3437.41 4726.72,3439.39 4729.42,3441.33 4733.64,3444.41 4733.64,3405.04 4729.42,3408.12 4726.72,3410.06 4723.72,3412.04 4720.48,3413.88 4717.07,3415.42 4713.56,3416.46 4711.79,3416.75
  region net GND: 4766.38,3718.03 4750.63,3718.03 4750.69,3725.71 4750.65,3729.66 4750.46,3733.39 4750.04,3736.67 4749.33,3739.29 4748.84,3740.28 4748.24,3741.03 4747.53,3741.49 4746.69,3741.65 4770.32,3741.65 4769.48,3741.49 4768.77,3741.03 4768.17,3740.28 4767.68,3739.29 4766.97,3736.67 4766.55,3733.39 4766.36,3729.66 4766.32,3725.71
  region net GND: 4750.63,3471.97 4766.38,3471.97 4766.32,3464.29 4766.36,3460.34 4766.55,3456.61 4766.97,3453.33 4767.68,3450.71 4768.17,3449.72 4768.77,3448.97 4769.48,3448.51 4770.32,3448.35 4746.69,3448.35 4747.53,3448.51 4748.24,3448.97 4748.84,3449.72 4749.33,3450.71 4750.04,3453.33 4750.46,3456.61 4750.65,3460.34 4750.69,3464.29
  region net GND: 4766.38,3377.48 4750.63,3377.48 4750.69,3385.16 4750.65,3389.11 4750.46,3392.84 4750.04,3396.12 4749.33,3398.74 4748.84,3399.73 4748.24,3400.48 4747.53,3400.94 4746.69,3401.1 4770.32,3401.1 4769.48,3400.94 4768.77,3400.48 4768.17,3399.73 4767.68,3398.74 4766.97,3396.12 4766.55,3392.84 4766.36,3389.11 4766.32,3385.16
  region net GND: 4750.63,3395.73 4766.38,3395.73 ccw(c4798.65,3395.73) 4776.66,3372.11 4738.82,3372.11 ccw(c4721.1,3395.73)
  region net GND: 4583.3,3447.36 4602.99,3447.36 4603.16,3447.09 4603.66,3446.88 4605.45,3446.57 4610.86,3446.38 4575.43,3446.38 4580.84,3446.57 4582.63,3446.88 4583.13,3447.09
  region net GND: 4600.1,3454.32 4580,3446.59 ccw(c4549.84,3413.18) 4549.84,3458.19 4593.15,3479.84 ccw(c4643.43,3479.84)
  region net GND: 4534.9,3373.55 4529.47,3353.98 ccw(c4551.55,3331.9) 4521.57,3340.66 4521.57,3365.66 ccw(c4512.82,3395.63)
  region net GND: 4573.26,3397.77 4554.83,3393.48 4556.38,3395.29 4557.79,3397.43 4559,3399.76 4559.97,3402.14 4560.62,3404.44 4560.91,3406.5 4560.77,3408.2 4560.52,3408.87 4560.14,3409.39 4589.17,3403.07 4585.86,3402.84 4583.78,3402.51 4581.55,3402.01 4579.27,3401.31 4577.06,3400.39 4575.02,3399.21
  region net USB_D+: 4547.85,3580 4547.85,3590 ccw(c4547.85,3592.4) 4549.84,3591.06 4549.84,3579.25 ccw(c4547.85,3576.98)
  region net USB_D+: 4548.08,3619.53 4548.08,3629.53 ccw(c4548.08,3631.69) 4549.84,3630.43 4549.84,3618.62 ccw(c4548.08,3617.36)
  region net USB_D-: 4594.74,3610 4594.74,3600 ccw(c4594.74,3598.27) 4593.15,3598.94 4593.15,3610.75 ccw(c4594.74,3612.07)
  region net +5V: 4706.63,3693.65 4696.63,3693.65 4696.28,3695.46 4695.38,3697.73 4694.09,3700.06 4692.62,3702.06 4710.63,3702.06 4709.16,3700.06 4707.88,3697.73 4706.97,3695.46
  region net +5V: 4597.42,3515.35 4600.13,3503.92 ccw(c4617.46,3486.59) 4593.15,3489.69 4593.15,3511.34 ccw(c4531.5,3581.27)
